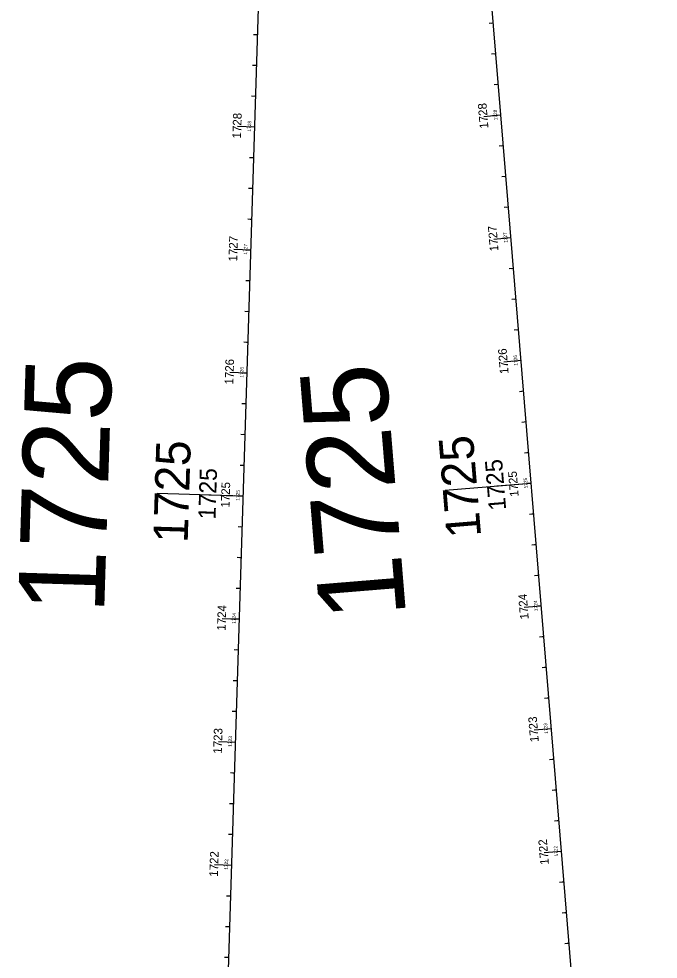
# Model space of a CAD drawing. Extents: x 353835 to 363333, y 126218 to 205387.
# Drawn here: x 361244 to 361763, y 131324 to 132088 of the extents above; entities that cross this region are included whole.
import ezdxf

# ---------------------------------------------------------------- set-up
doc = ezdxf.new("R2010")
doc.units = 0
for name, color, linetype in [('P_ALI_100_Sta', 7, 'Continuous'), ('P_ALI_100_Tic', 7, 'Continuous'), ('P_ALI_20', 7, 'Continuous'), ('P_ALI_200_Sta', 7, 'Continuous'), ('P_ALI_200_Tic', 7, 'Continuous'), ('P_ALI_20_Sta', 7, 'Continuous'), ('P_ALI_20_Tic', 7, 'Continuous'), ('P_ALI_500_Sta', 7, 'Continuous'), ('P_ALI_50_Sta', 7, 'Continuous'), ('P_ALI_50_Tic', 7, 'Continuous')]:
    doc.layers.add(name, color=color, linetype=linetype)

msp = doc.modelspace()

# ---------------------------------------------------------------- linework, layer by layer
for points in [[(361635.3, 132009.61), (361635.32, 132009.61)], [(361643.47, 131909.95), (361643.49, 131909.95)], [(361651.65, 131810.28), (361651.67, 131810.28)], [(361668, 131610.95), (361668.02, 131610.95)], [(361676.18, 131511.28), (361676.2, 131511.29)], [(361684.35, 131411.62), (361684.37, 131411.62)]]:
    msp.add_lwpolyline(points)
at = {"layer": 'P_ALI_100_Tic'}
for points in [[(361628.33, 132009.04), (361635.31, 132009.61)], [(361428.54, 132000.21), (361435.54, 131999.99)], [(361636.51, 131909.37), (361643.48, 131909.95)], [(361425.42, 131900.26), (361432.42, 131900.04)], [(361644.68, 131809.71), (361651.66, 131810.28)], [(361422.3, 131800.31), (361429.3, 131800.09)], [(361590.07, 131704.89), (361659.83, 131710.62)], [(361645.88, 131709.47), (361659.83, 131710.62)], [(361356.21, 131702.32), (361426.18, 131700.14)], [(361412.19, 131700.57), (361426.18, 131700.14)], [(361661.03, 131610.38), (361668.01, 131610.95)], [(361416.06, 131600.4), (361423.06, 131600.19)], [(361669.21, 131510.71), (361676.19, 131511.29)], [(361412.94, 131500.45), (361419.94, 131500.23)], [(361677.39, 131411.05), (361684.36, 131411.62)], [(361409.82, 131400.5), (361416.82, 131400.28)]]:
    msp.add_lwpolyline(points, dxfattribs=at)
at = {"layer": 'P_ALI_20'}
for p, q in [((361371.19, 129938.32), (361462, 132847.85)), ((361762.92, 130454.08), (361568.24, 132827.16))]:
    msp.add_line(p, q, dxfattribs=at)
at = {"layer": 'P_ALI_200_Tic'}
for points in [[(361621.35, 132008.47), (361635.31, 132009.61)], [(361421.55, 132000.43), (361435.54, 131999.99)], [(361629.53, 131908.8), (361643.48, 131909.95)], [(361418.43, 131900.48), (361432.42, 131900.04)], [(361637.71, 131809.14), (361651.66, 131810.28)], [(361415.31, 131800.52), (361429.3, 131800.09)], [(361631.93, 131708.33), (361659.83, 131710.62)], [(361398.19, 131701.01), (361426.18, 131700.14)], [(361654.06, 131609.81), (361668.01, 131610.95)], [(361409.07, 131600.62), (361423.06, 131600.19)], [(361662.23, 131510.14), (361676.19, 131511.29)], [(361405.95, 131500.67), (361419.94, 131500.23)], [(361670.41, 131410.48), (361684.36, 131411.62)], [(361402.83, 131400.72), (361416.82, 131400.28)]]:
    msp.add_lwpolyline(points, dxfattribs=at)
at = {"layer": 'P_ALI_20_Tic'}
for points in [[(361627.78, 132084.25), (361629.17, 132084.36)], [(361436.48, 132075), (361437.88, 132074.95)], [(361629.82, 132059.33), (361631.22, 132059.44)], [(361435.7, 132050.01), (361437.1, 132049.97)], [(361631.87, 132034.41), (361633.26, 132034.53)], [(361434.92, 132025.02), (361436.32, 132024.98)], [(361632.52, 132009.38), (361635.31, 132009.61)], [(361432.74, 132000.08), (361435.54, 131999.99)], [(361635.96, 131984.58), (361637.35, 131984.69)], [(361433.36, 131975.05), (361434.76, 131975)], [(361638, 131959.66), (361639.39, 131959.78)], [(361432.58, 131950.06), (361433.98, 131950.02)], [(361640.04, 131934.75), (361641.44, 131934.86)], [(361431.8, 131925.07), (361433.2, 131925.03)], [(361640.69, 131909.72), (361643.48, 131909.95)], [(361429.62, 131900.13), (361432.42, 131900.04)], [(361644.13, 131884.92), (361645.53, 131885.03)], [(361430.24, 131875.1), (361431.64, 131875.05)], [(361646.18, 131860), (361647.57, 131860.11)], [(361429.46, 131850.11), (361430.86, 131850.06)], [(361648.22, 131835.08), (361649.61, 131835.2)], [(361428.68, 131825.12), (361430.08, 131825.08)], [(361648.87, 131810.05), (361651.66, 131810.28)], [(361426.5, 131800.18), (361429.3, 131800.09)], [(361652.31, 131785.25), (361653.7, 131785.36)], [(361427.12, 131775.14), (361428.52, 131775.1)], [(361654.35, 131760.33), (361655.75, 131760.45)], [(361426.34, 131750.16), (361427.74, 131750.11)], [(361656.4, 131735.42), (361657.79, 131735.53)], [(361425.56, 131725.17), (361426.96, 131725.12)], [(361657.04, 131710.39), (361659.83, 131710.62)], [(361423.38, 131700.22), (361426.18, 131700.14)], [(361660.48, 131685.58), (361661.88, 131685.7)], [(361424, 131675.19), (361425.4, 131675.15)], [(361662.53, 131660.67), (361663.92, 131660.78)], [(361423.22, 131650.2), (361424.62, 131650.16)], [(361664.57, 131635.75), (361665.97, 131635.87)], [(361422.44, 131625.22), (361423.84, 131625.17)], [(361665.22, 131610.72), (361668.01, 131610.95)], [(361420.26, 131600.27), (361423.06, 131600.19)], [(361668.66, 131585.92), (361670.05, 131586.03)], [(361420.88, 131575.24), (361422.28, 131575.2)], [(361670.7, 131561), (361672.1, 131561.12)], [(361420.1, 131550.25), (361421.5, 131550.21)], [(361672.75, 131536.09), (361674.14, 131536.2)], [(361419.32, 131525.27), (361420.72, 131525.22)], [(361673.4, 131511.06), (361676.19, 131511.29)], [(361417.14, 131500.32), (361419.94, 131500.23)], [(361676.84, 131486.25), (361678.23, 131486.37)], [(361417.76, 131475.29), (361419.16, 131475.25)], [(361678.88, 131461.34), (361680.27, 131461.45)], [(361416.98, 131450.3), (361418.38, 131450.26)], [(361680.92, 131436.42), (361682.32, 131436.54)], [(361416.2, 131425.31), (361417.6, 131425.27)], [(361681.57, 131411.39), (361684.36, 131411.62)], [(361414.02, 131400.37), (361416.82, 131400.28)], [(361685.01, 131386.59), (361686.41, 131386.7)], [(361414.64, 131375.34), (361416.04, 131375.29)], [(361687.06, 131361.67), (361688.45, 131361.79)], [(361413.86, 131350.35), (361415.26, 131350.31)], [(361689.1, 131336.76), (361690.5, 131336.87)], [(361413.08, 131325.36), (361414.48, 131325.32)]]:
    msp.add_lwpolyline(points, dxfattribs=at)
at = {"layer": 'P_ALI_50_Tic'}
for points in [[(361625.69, 132084.07), (361629.17, 132084.36)], [(361434.38, 132075.06), (361437.88, 132074.95)], [(361434.38, 132075.06), (361437.88, 132074.95)], [(361627.73, 132059.16), (361631.22, 132059.44)], [(361433.6, 132050.08), (361437.1, 132049.97)], [(361433.6, 132050.08), (361437.1, 132049.97)], [(361629.77, 132034.24), (361633.26, 132034.53)], [(361432.82, 132025.09), (361436.32, 132024.98)], [(361432.82, 132025.09), (361436.32, 132024.98)], [(361628.33, 132009.04), (361635.31, 132009.61)], [(361428.54, 132000.21), (361435.54, 131999.99)], [(361428.54, 132000.21), (361435.54, 131999.99)], [(361633.86, 131984.41), (361637.35, 131984.69)], [(361431.26, 131975.11), (361434.76, 131975)], [(361431.26, 131975.11), (361434.76, 131975)], [(361635.91, 131959.49), (361639.39, 131959.78)], [(361430.48, 131950.12), (361433.98, 131950.02)], [(361430.48, 131950.12), (361433.98, 131950.02)], [(361637.95, 131934.58), (361641.44, 131934.86)], [(361429.7, 131925.14), (361433.2, 131925.03)], [(361429.7, 131925.14), (361433.2, 131925.03)], [(361636.51, 131909.37), (361643.48, 131909.95)], [(361425.42, 131900.26), (361432.42, 131900.04)], [(361425.42, 131900.26), (361432.42, 131900.04)], [(361642.04, 131884.74), (361645.53, 131885.03)], [(361428.14, 131875.16), (361431.64, 131875.05)], [(361428.14, 131875.16), (361431.64, 131875.05)], [(361644.08, 131859.83), (361647.57, 131860.11)], [(361427.36, 131850.17), (361430.86, 131850.06)], [(361427.36, 131850.17), (361430.86, 131850.06)], [(361646.13, 131834.91), (361649.61, 131835.2)], [(361426.58, 131825.19), (361430.08, 131825.08)], [(361426.58, 131825.19), (361430.08, 131825.08)], [(361644.68, 131809.71), (361651.66, 131810.28)], [(361422.3, 131800.31), (361429.3, 131800.09)], [(361422.3, 131800.31), (361429.3, 131800.09)], [(361650.21, 131785.08), (361653.7, 131785.36)], [(361425.02, 131775.21), (361428.52, 131775.1)], [(361425.02, 131775.21), (361428.52, 131775.1)], [(361652.26, 131760.16), (361655.75, 131760.45)], [(361424.24, 131750.22), (361427.74, 131750.11)], [(361424.24, 131750.22), (361427.74, 131750.11)], [(361654.3, 131735.25), (361657.79, 131735.53)], [(361423.46, 131725.23), (361426.96, 131725.12)], [(361423.46, 131725.23), (361426.96, 131725.12)], [(361652.86, 131710.04), (361659.83, 131710.62)], [(361419.18, 131700.36), (361426.18, 131700.14)], [(361419.18, 131700.36), (361426.18, 131700.14)], [(361658.39, 131685.41), (361661.88, 131685.7)], [(361421.9, 131675.26), (361425.4, 131675.15)], [(361421.9, 131675.26), (361425.4, 131675.15)], [(361660.43, 131660.5), (361663.92, 131660.78)], [(361421.12, 131650.27), (361424.62, 131650.16)], [(361421.12, 131650.27), (361424.62, 131650.16)], [(361662.48, 131635.58), (361665.97, 131635.87)], [(361420.34, 131625.28), (361423.84, 131625.17)], [(361420.34, 131625.28), (361423.84, 131625.17)], [(361661.03, 131610.38), (361668.01, 131610.95)], [(361416.06, 131600.4), (361423.06, 131600.19)], [(361416.06, 131600.4), (361423.06, 131600.19)], [(361666.57, 131585.75), (361670.05, 131586.03)], [(361418.78, 131575.31), (361422.28, 131575.2)], [(361418.78, 131575.31), (361422.28, 131575.2)], [(361668.61, 131560.83), (361672.1, 131561.12)], [(361418, 131550.32), (361421.5, 131550.21)], [(361418, 131550.32), (361421.5, 131550.21)], [(361670.65, 131535.92), (361674.14, 131536.2)], [(361417.22, 131525.33), (361420.72, 131525.22)], [(361417.22, 131525.33), (361420.72, 131525.22)], [(361669.21, 131510.71), (361676.19, 131511.29)], [(361412.94, 131500.45), (361419.94, 131500.23)], [(361412.94, 131500.45), (361419.94, 131500.23)], [(361674.74, 131486.08), (361678.23, 131486.37)], [(361415.66, 131475.36), (361419.16, 131475.25)], [(361415.66, 131475.36), (361419.16, 131475.25)], [(361676.79, 131461.17), (361680.27, 131461.45)], [(361414.88, 131450.37), (361418.38, 131450.26)], [(361414.88, 131450.37), (361418.38, 131450.26)], [(361678.83, 131436.25), (361682.32, 131436.54)], [(361414.1, 131425.38), (361417.6, 131425.27)], [(361414.1, 131425.38), (361417.6, 131425.27)], [(361677.39, 131411.05), (361684.36, 131411.62)], [(361409.82, 131400.5), (361416.82, 131400.28)], [(361409.82, 131400.5), (361416.82, 131400.28)], [(361682.92, 131386.42), (361686.41, 131386.7)], [(361412.54, 131375.4), (361416.04, 131375.29)], [(361412.54, 131375.4), (361416.04, 131375.29)], [(361684.96, 131361.5), (361688.45, 131361.79)], [(361411.76, 131350.42), (361415.26, 131350.31)], [(361411.76, 131350.42), (361415.26, 131350.31)], [(361687.01, 131336.58), (361690.5, 131336.87)], [(361410.98, 131325.43), (361414.48, 131325.32)], [(361410.98, 131325.43), (361414.48, 131325.32)]]:
    msp.add_lwpolyline(points, dxfattribs=at)

# ---------------------------------------------------------------- texts
at = {"layer": 'P_ALI_100_Sta'}
for rotation, p in [(94.68978, (361639.54, 131688.93)), (88.21215, (361403.57, 131680.88))]:
    msp.add_text('1725', height=14, rotation=rotation, dxfattribs=at).set_placement(p)
at = {"layer": 'P_ALI_200_Sta'}
for rotation, p in [(94.68978, (361619.24, 131667.25)), (88.21215, (361380.96, 131661.62))]:
    msp.add_text('1725', height=28, rotation=rotation, dxfattribs=at).set_placement(p)
at = {"layer": 'P_ALI_20_Sta'}
for s, rotation, p in [('1728', 94.68978, (361632.56, 132005.38)), ('1728', 88.21215, (361432.34, 131996.1)), ('1727', 94.68978, (361640.74, 131905.72)), ('1727', 88.21215, (361429.22, 131896.15)), ('1726', 94.68978, (361648.91, 131806.06)), ('1726', 88.21215, (361426.1, 131796.21)), ('1725', 94.68978, (361657.09, 131706.39)), ('1725', 88.21215, (361422.98, 131696.24)), ('1724', 94.68978, (361665.27, 131606.72)), ('1724', 88.21215, (361419.86, 131596.29)), ('1723', 94.68978, (361673.44, 131507.06)), ('1723', 88.21215, (361416.74, 131496.34)), ('1722', 94.68978, (361681.62, 131407.39)), ('1722', 88.21215, (361413.62, 131396.39))]:
    msp.add_text(s, height=2.8, rotation=rotation, dxfattribs=at).set_placement(p)
at = {"layer": 'P_ALI_500_Sta'}
for rotation, p in [(88.21215, (361313.12, 131603.85)), (94.68978, (361558.36, 131602.19))]:
    msp.add_text('1725', height=70, rotation=rotation, dxfattribs=at).set_placement(p)
at = {"layer": 'P_ALI_50_Sta'}
for s, rotation, p in [('1728', 94.68978, (361625.16, 131998.77)), ('1728', 88.21215, (361424.23, 131990.36)), ('1728', 88.21215, (361424.23, 131990.36)), ('1727', 94.68978, (361633.34, 131899.1)), ('1727', 88.21215, (361421.11, 131890.41)), ('1727', 88.21215, (361421.11, 131890.41)), ('1726', 94.68978, (361641.51, 131799.47)), ('1726', 88.21215, (361418, 131790.49)), ('1726', 88.21215, (361418, 131790.49)), ('1725', 94.68978, (361649.69, 131699.77)), ('1725', 88.21215, (361414.87, 131690.51)), ('1725', 88.21215, (361414.87, 131690.51)), ('1724', 94.68978, (361657.86, 131600.11)), ('1724', 88.21215, (361411.75, 131590.56)), ('1724', 88.21215, (361411.75, 131590.56)), ('1723', 94.68978, (361666.04, 131500.44)), ('1723', 88.21215, (361408.63, 131490.61)), ('1723', 88.21215, (361408.63, 131490.61)), ('1722', 94.68978, (361674.22, 131400.78)), ('1722', 88.21215, (361405.51, 131390.65)), ('1722', 88.21215, (361405.51, 131390.65))]:
    msp.add_text(s, height=7, rotation=rotation, dxfattribs=at).set_placement(p)

doc.saveas('drawing.dxf')
